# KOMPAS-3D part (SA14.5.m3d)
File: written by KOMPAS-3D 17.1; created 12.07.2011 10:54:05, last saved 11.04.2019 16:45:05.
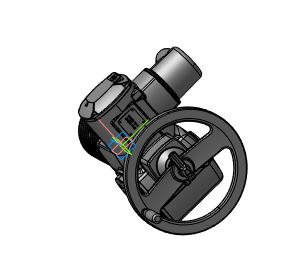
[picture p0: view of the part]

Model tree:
1. Плоскость XY
2. Плоскость ZX
3. Плоскость ZY
4. Ось X
5. Ось Y
6. Ось Z
7. Начало координат
8. Операция без истории:2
